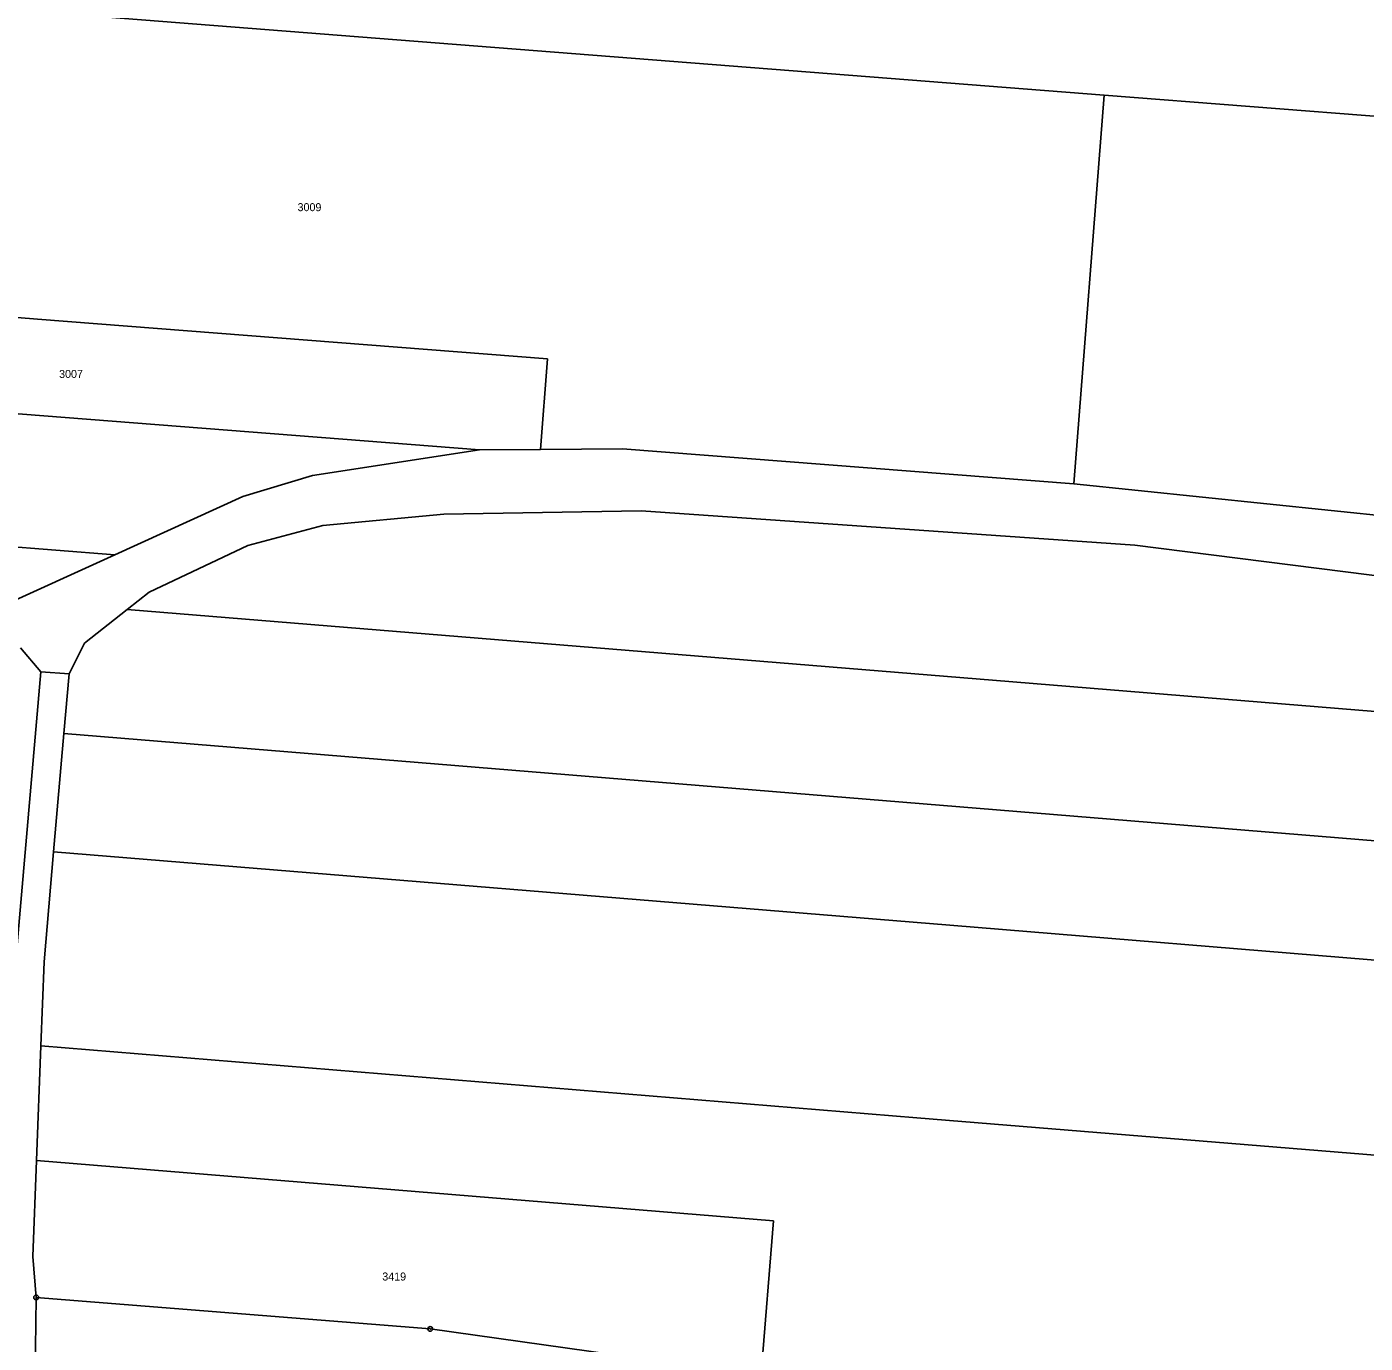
# Model space of a CAD drawing. Extents: x -618848 to -615803, y -1044450 to -1042254.
# Drawn here: x -618442.8 to -618158.6, y -1043276.7 to -1042997.1 of the extents above; entities that cross this region are included whole.
import ezdxf

# ---------------------------------------------------------------- set-up
doc = ezdxf.new("R2010")
doc.units = 0
doc.header["$LTSCALE"] = 0.68
doc.layers.add('1', color=7, linetype='Continuous', lineweight=25)
doc.layers.add('8', color=7, linetype='Continuous', lineweight=25)
doc.layers.add('2', color=7, linetype='Continuous')

msp = doc.modelspace()

# ---------------------------------------------------------------- linework, layer by layer
at = {"layer": '1'}
for p, q in [((-618530.67, -1042986.81), (-618372.36, -1042999.18)), ((-618372.36, -1042999.18), (-618214.04, -1043011.55)), ((-618220.5, -1043094.13), (-618214.04, -1043011.55)), ((-618214.04, -1043011.55), (-618062.37, -1043023.4)), ((-618440.56, -1043059.14), (-618548.9, -1043050.68)), ((-618332.22, -1043067.61), (-618440.56, -1043059.14)), ((-618333.72, -1043086.84), (-618332.22, -1043067.61)), ((-618453.04, -1043078.64), (-618346.67, -1043086.95)), ((-618346.67, -1043086.95), (-618382.13, -1043092.37)), ((-618346.67, -1043086.95), (-618333.72, -1043086.84)), ((-618316.3, -1043086.7), (-618333.72, -1043086.84)), ((-618220.5, -1043094.13), (-618316.3, -1043086.7)), ((-618382.13, -1043092.37), (-618396.92, -1043096.85)), ((-618148.98, -1043101.59), (-618220.5, -1043094.13)), ((-618424.1, -1043109.22), (-618577.64, -1043097.22)), ((-618396.92, -1043096.85), (-618424.1, -1043109.22)), ((-618354.22, -1043100.62), (-618312.36, -1043099.9)), ((-618312.36, -1043099.9), (-618207.51, -1043107.14)), ((-618379.95, -1043102.98), (-618354.22, -1043100.62)), ((-618395.87, -1043107.21), (-618379.95, -1043102.98)), ((-618416.84, -1043117.12), (-618395.87, -1043107.21)), ((-618207.51, -1043107.14), (-618150.88, -1043114.38)), ((-618472.26, -1043131.14), (-618424.1, -1043109.22)), ((-618421.47, -1043120.8), (-618416.84, -1043117.12)), ((-618430.53, -1043128), (-618421.47, -1043120.8)), ((-618421.47, -1043120.8), (-618233.44, -1043136.2)), ((-618433.83, -1043134.47), (-618430.53, -1043128)), ((-618444.12, -1043128.96), (-618439.81, -1043134.07)), ((-618445.12, -1043195.3), (-618439.81, -1043134.07)), ((-618439.81, -1043134.07), (-618433.83, -1043134.47)), ((-618434.92, -1043147.16), (-618433.83, -1043134.47)), ((-618233.44, -1043136.2), (-618045.41, -1043151.59)), ((-618437.12, -1043172.31), (-618434.92, -1043147.16)), ((-618244.65, -1043162.74), (-618434.92, -1043147.16)), ((-618054.37, -1043178.32), (-618244.65, -1043162.74)), ((-618439.13, -1043195.67), (-618437.12, -1043172.31)), ((-618437.12, -1043172.31), (-618246.82, -1043187.9)), ((-618246.82, -1043187.9), (-618056.52, -1043203.48)), ((-618439.81, -1043213.55), (-618439.13, -1043195.67)), ((-618440.74, -1043237.88), (-618439.81, -1043213.55)), ((-618253.78, -1043228.78), (-618439.81, -1043213.55)), ((-618067.75, -1043244.02), (-618253.78, -1043228.78)), ((-618441.51, -1043258.27), (-618440.74, -1043237.88)), ((-618440.74, -1043237.88), (-618284.22, -1043250.69)), ((-618284.22, -1043250.69), (-618286.9, -1043283.48)), ((-618440.82, -1043266.96), (-618441.51, -1043258.27)), ((-618441.14, -1043289.66), (-618440.82, -1043266.96)), ((-618357.13, -1043273.65), (-618440.82, -1043266.96)), ((-618286.9, -1043283.48), (-618357.13, -1043273.65))]:
    msp.add_line(p, q, dxfattribs=at)
at = {"layer": '8'}
for centre, radius in [((-618440.82, -1043266.9599), 0.5), ((-618440.82, -1043266.9599), 0.0303), ((-618357.13, -1043273.6499), 0.5), ((-618357.13, -1043273.6499), 0.0303)]:
    msp.add_circle(centre, radius, dxfattribs=at)

# ---------------------------------------------------------------- texts
at = {"layer": '2'}
for s, p in [('3009', (-618385.31, -1043036.225)), ('3007', (-618435.95, -1043071.655)), ('3419', (-618367.32, -1043263.365))]:
    msp.add_text(s, height=1.7, dxfattribs=at).set_placement(p)

doc.saveas('drawing.dxf')
